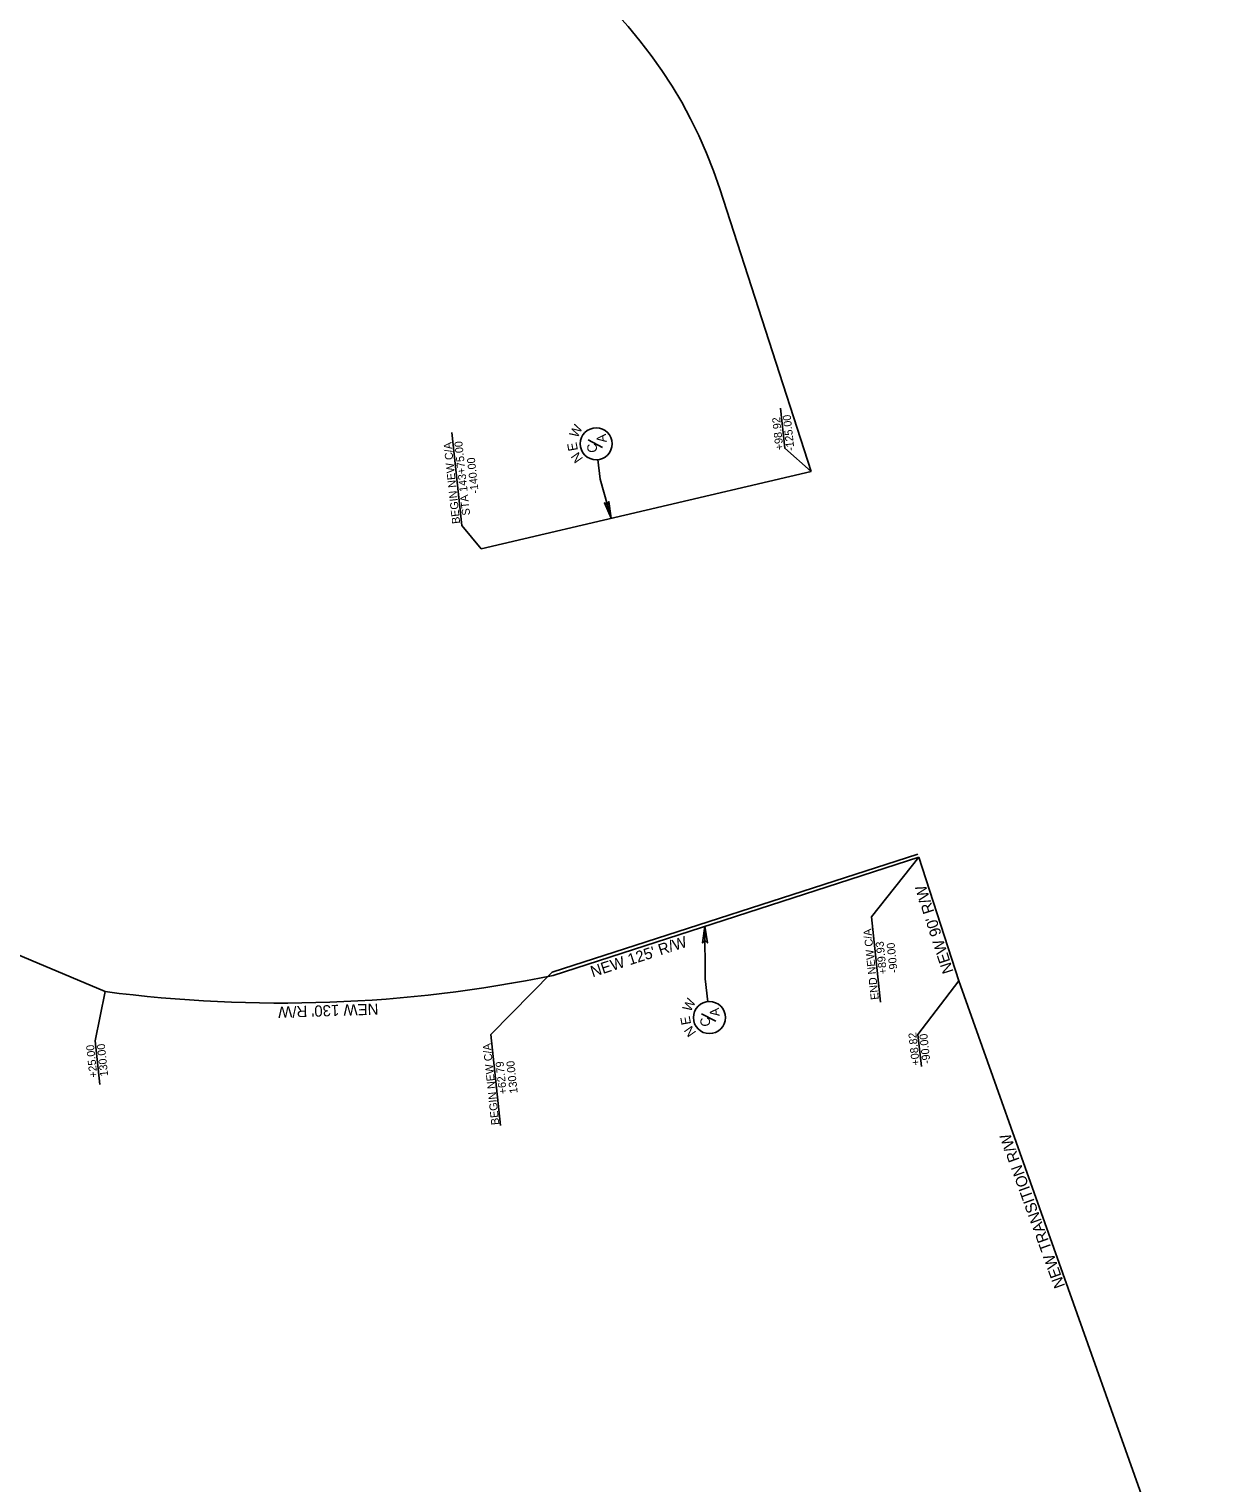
# Model space of a CAD drawing. Extents: x 2003184 to 2010449, y 855784 to 861212.
# Drawn here: x 2004187 to 2004925, y 857270 to 858179 of the extents above; entities that cross this region are included whole.
import ezdxf

# ---------------------------------------------------------------- set-up
doc = ezdxf.new("R2010")
doc.units = 0
for name, color, linetype in [('RD_PD_Control_Access', 7, 'Continuous'), ('RD_PD_RW', 7, 'Continuous'), ('RD_PD_RW_TX', 7, 'Continuous')]:
    doc.layers.add(name, color=color, linetype=linetype)

msp = doc.modelspace()

# ---------------------------------------------------------------- linework, layer by layer
at = {"layer": 'RD_PD_Control_Access'}
for p, q in [((2004675.48, 857902.35), (2004618.45, 858078.81)), ((2004536.27, 857922.06), (2004545.19, 857917.36)), ((2004469.37, 857854.04), (2004675.48, 857902.35)), ((2004513.73, 857589.45), (2004742.22, 857663.29)), ((2004606.95, 857563.58), (2004615.88, 857558.88))]:
    msp.add_line(p, q, dxfattribs=at)
for points in [[(2004451.08, 857926.68), (2004457.33, 857868.46), (2004469.37, 857854.04)], [(2004542.32, 857909.69), (2004543.62, 857897.51), (2004550.64, 857873.09)], [(2004718.9, 857570.75), (2004713.17, 857624.18), (2004742.84, 857661.39)], [(2004610.87, 857571.1), (2004609.33, 857585.39), (2004609.15, 857618.19)], [(2004481.48, 857493.67), (2004475.38, 857550.52), (2004513.73, 857589.45)]]:
    msp.add_lwpolyline(points, dxfattribs=at)
for points in [[(2004550.64, 857873.09), (2004549.21, 857883.49), (2004548.21, 857881.54), (2004546.33, 857882.66)], [(2004609.15, 857618.19), (2004607.71, 857607.79), (2004609.2, 857609.4), (2004610.71, 857607.81)]]:
    msp.add_lwpolyline(points, close=True, dxfattribs=at)
for centre in [(2004541.25, 857919.63), (2004611.94, 857561.15)]:
    msp.add_circle(centre, 10, dxfattribs=at)
msp.add_arc((2004341.55, 857989.33), 291, 17.90874, 91.2081, dxfattribs=at)
at = {"layer": 'RD_PD_RW'}
for p, q in [((2004514.35, 857587.55), (2004742.84, 857661.39)), ((2004767.78, 857584.21), (2004742.84, 857661.39)), ((2004234.57, 857577.41), (2004045.77, 857657.19)), ((2004924.58, 857142.67), (2004767.78, 857584.21))]:
    msp.add_line(p, q, dxfattribs=at)
msp.add_arc((2004344.41, 858411.2), 841, 262.49547, 281.65788, dxfattribs=at)
at = {"layer": 'RD_PD_RW_TX'}
for points in [[(2004656.32, 857941.96), (2004659.02, 857916.86), (2004675.48, 857902.35)], [(2004744.32, 857530.65), (2004742.18, 857550.54), (2004767.78, 857584.21)], [(2004231.1, 857519.31), (2004228.17, 857546.53), (2004234.57, 857577.41)]]:
    msp.add_lwpolyline(points, dxfattribs=at)

# ---------------------------------------------------------------- texts
at = {"layer": 'RD_PD_Control_Access'}
for s, height, rotation, p in [('+98.92', 5, 96.12511, (2004658.24, 857915.93)), ('-125.00', 5, 96.12511, (2004665.08, 857915.44)), ('W', 6, 62.64133, (2004529.48, 857922.84)), ('A', 6, 96.12511, (2004547.78, 857920.66)), ('BEGIN NEW C/A', 5, 96.12511, (2004456.27, 857869.87)), ('STA 143+75.00', 5, 96.12511, (2004462.5, 857875.1)), ('E', 6, 100.31882, (2004529.85, 857915.63)), ('C', 6, 96.12511, (2004541.98, 857914.36)), ('-140.00', 5, 96.12511, (2004467.83, 857888.73)), ('N', 6, 125.43714, (2004533.24, 857910.32)), ('END NEW C/A', 5, 96.12511, (2004717.79, 857572.53)), ('+89.93', 5, 96.12511, (2004722.87, 857588.48)), ('-90.00', 5, 96.12511, (2004729.57, 857589.32)), ('W', 6, 62.64133, (2004600.17, 857564.35)), ('E', 6, 100.31882, (2004600.54, 857557.15)), ('C', 6, 96.12511, (2004612.66, 857555.88)), ('A', 6, 96.12511, (2004618.46, 857562.17)), ('N', 6, 125.43714, (2004603.92, 857551.84)), ('BEGIN NEW C/A', 5, 96.12511, (2004480.74, 857494.31)), ('+08.82', 5, 96.12511, (2004743.34, 857531.52)), ('-90.00', 5, 96.12511, (2004750.03, 857532.48)), ('130.00 ', 5, 96.12511, (2004492.2, 857514.07)), ('+62.79', 5, 96.12511, (2004485.46, 857513.55))]:
    msp.add_text(s, height=height, rotation=rotation, dxfattribs=at).set_placement(p)
at = {"layer": 'RD_PD_RW_TX'}
for s, height, rotation, p in [("NEW 90' R/W", 7, 107.90874, (2004764.54, 857589.9)), ("NEW 125' R/W", 7, 17.90874, (2004538.99, 857586.3)), ("NEW 130' R/W", 7, 181.86023, (2004405.07, 857569.98)), ('+25.00', 5, 96.12511, (2004229.72, 857523.9)), ('130.00', 5, 96.12511, (2004236.42, 857524.72)), ('NEW TRANSITION R/W', 7, 109.86378, (2004834.25, 857393.54))]:
    msp.add_text(s, height=height, rotation=rotation, dxfattribs=at).set_placement(p)

doc.saveas('drawing.dxf')
